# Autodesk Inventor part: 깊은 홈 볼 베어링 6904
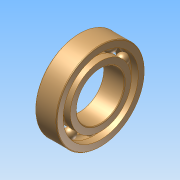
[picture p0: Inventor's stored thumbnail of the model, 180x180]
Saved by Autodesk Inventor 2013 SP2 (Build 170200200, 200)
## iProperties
Created: 2025-09
Part Number: 깊은 홈 볼 베어링 6904
Material: Generic
Document SubType Name: Modeling
Designer: a
Density: 1 g/cm^3
Author: a
변환 표준: STEP AP214IS
전처리기: Build: 200, Release: 2013 SP2 Update 6 - Date: Thu 07/17/2014
전송 단위: 밀리미터
불확실성: 0.01
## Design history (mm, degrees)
node "깊은 홈 볼 베어링 69041"
body "Solid1"
node "Solid1_1"
node "Solid1_2"
node "Solid1_3"
node "Solid1_4"
node "Solid1_5"
node "Solid1_6"
node "Solid1_7"
node "Solid1_8"
node "Solid1_9"
node "Solid1_10"
node "Solid1_11"
node "기준1"
node "기준2"
node "기준3"
node "기준4"
node "기준5"
node "기준6"
node "기준7"
node "기준8"
node "기준9"
node "기준10"
node "기준11"
node "기준12"
